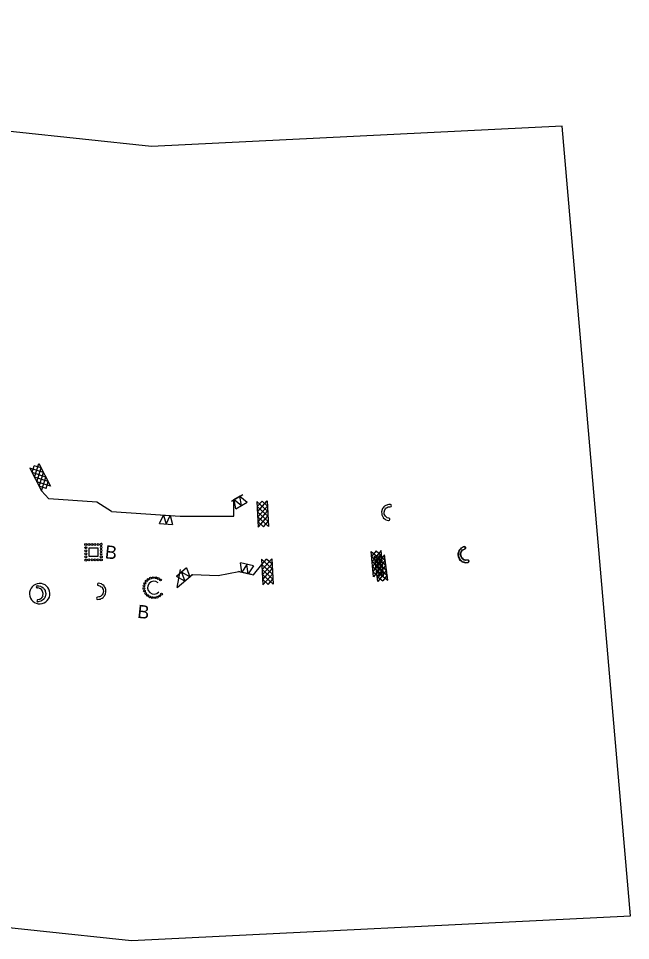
# Model space of a CAD drawing. Extents: x 2283629 to 2286552, y 529718 to 531440.
# Drawn here: x 2285858 to 2286552, y 529718 to 530763 of the extents above; entities that cross this region are included whole.
import ezdxf

# ---------------------------------------------------------------- set-up
doc = ezdxf.new("R2010")
doc.units = 0
for name, color, linetype in [('_CIVIL_CONSTRUCTION', 7, 'Continuous'), ('Draft_Corridor_Graphics_Design', 7, 'Continuous'), ('Draft_Corridor_Graphics_Final', 7, 'Continuous'), ('E_NCDOT_Vertical_Profile_Ground_Line', 7, 'Continuous'), ('P_NCDOT_Terrain_Exterior', 7, 'Continuous'), ('P_NCDOT_Terrain_Model_Triangles', 7, 'Continuous'), ('P_NCDOT_Terrain_Triangle_Vertices', 7, 'Continuous'), ('P_NCDOT_Terrain_Void', 7, 'Continuous'), ('P_RDY_Slope_Stake_Fill_Limits', 7, 'Continuous'), ('P_RDY_TC_Pvmt_Asphalt_Base_Course_Wedge', 7, 'Continuous'), ('P_RDY_TC_Pvmt_Asphalt_Intermediate_Course_Wedge', 7, 'Continuous'), ('P_RDY_TL_Paved_Shoulder_Sub', 7, 'Continuous'), ('P_RDY_TL_Sidewalk', 7, 'Continuous'), ('Scratch_Level_5', 7, 'Continuous')]:
    doc.layers.add(name, color=color, linetype=linetype)

msp = doc.modelspace()

# ---------------------------------------------------------------- linework, layer by layer
at = {"layer": '_CIVIL_CONSTRUCTION'}
msp.add_lwpolyline([(2285237.1, 530763.3), (2285008.8, 530132), (2284997.4, 530131.2), (2285004.2, 530031.4), (2284931, 529916.9), (2285450.5, 529775.1), (2285986, 529718.4), (2286551.7, 529746.5), (2286474.3, 530641.3), (2286008.6, 530618.1), (2285617, 530659.6)], close=True, dxfattribs=at)
at = {"layer": 'Draft_Corridor_Graphics_Final'}
for p, q in [((2286358.9, 530156.6), (2286359.2, 530157.7)), ((2286359.2, 530153.9), (2286359.1, 530154)), ((2286359.5, 530158.8), (2286359.6, 530159)), ((2286365, 530149.2), (2286364.6, 530149.2))]:
    msp.add_line(p, q, dxfattribs=at)
for points in [[(2286362.4, 530164.5), (2286361, 530163.8), (2286359.4, 530163), (2286358.9, 530162.4), (2286358, 530161.4), (2286357, 530160.2), (2286357, 530160.2), (2286356.9, 530159.9), (2286356.9, 530159.7), (2286356.7, 530159), (2286356.4, 530158.1), (2286356.3, 530157.9), (2286356, 530156.8), (2286356, 530155.8), (2286356.3, 530153.1), (2286356.3, 530153.1), (2286357.4, 530150.9), (2286357.9, 530149.9), (2286359, 530149), (2286359.5, 530148.5), (2286360.3, 530147.9), (2286360.3, 530147.9), (2286360.6, 530147.6), (2286360.7, 530147.5), (2286362.4, 530147), (2286363.4, 530146.7), (2286364.2, 530146.5), (2286366, 530146.7), (2286367.5, 530146.9)], [(2286366.8, 530149.4), (2286365, 530149.2), (2286364.6, 530149.2), (2286363.2, 530149.6), (2286362.2, 530149.9), (2286361.1, 530150.9), (2286360.3, 530151.7), (2286359.2, 530153.9), (2286359.1, 530154), (2286358.9, 530156.6), (2286359.2, 530157.7), (2286359.5, 530158.8), (2286359.6, 530159), (2286360.5, 530160.1), (2286361.2, 530161), (2286361.9, 530161.3), (2286363.3, 530162), (2286363.3, 530162)]]:
    msp.add_lwpolyline(points, dxfattribs=at)
for centre, radius, start in [((2286362.8, 530163.2), 1.33, 294.9625), ((2286367.2, 530148.1), 1.3, 286.0751)]:
    msp.add_arc(centre, radius, start, 106.0751, dxfattribs=at)
at = {"layer": 'E_NCDOT_Vertical_Profile_Ground_Line'}
for p, q in [((2286099.1, 530216.3), (2286112, 530223.8)), ((2286104.1, 530207.6), (2286102.3, 530218.2)), ((2286102.3, 530218.2), (2286110.6, 530211.4)), ((2286104.1, 530207.6), (2286117.1, 530215.2)), ((2286110.6, 530211.4), (2286108.8, 530221.9)), ((2286108.8, 530221.9), (2286117.1, 530215.2)), ((2286017.5, 530190.9), (2286022.1, 530200.6)), ((2286018.3, 530200.9), (2286033.3, 530199.7)), ((2286022.1, 530200.6), (2286025, 530190.3)), ((2286025, 530190.3), (2286029.5, 530200)), ((2286029.5, 530200), (2286032.4, 530189.7)), ((2286017.5, 530190.9), (2286032.4, 530189.7)), ((2286124.1, 530143), (2286109.5, 530146.3)), ((2286110.9, 530135.8), (2286109.5, 530146.3)), ((2286116.8, 530144.7), (2286110.9, 530135.8)), ((2286118.2, 530134.1), (2286116.8, 530144.7)), ((2286124.1, 530143), (2286118.2, 530134.1)), ((2286048.2, 530140.7), (2286036.9, 530130.8)), ((2286046.3, 530125.7), (2286036.9, 530130.8)), ((2286052, 530130.7), (2286042.6, 530135.7)), ((2286042.6, 530135.7), (2286046.3, 530125.7)), ((2286054.8, 530133.1), (2286043.5, 530123.3)), ((2286048.2, 530140.7), (2286052, 530130.7)), ((2286121.9, 530133.3), (2286107.3, 530136.6))]:
    msp.add_line(p, q, dxfattribs=at)
at = {"layer": 'P_NCDOT_Terrain_Exterior'}
for p, q in [((2285873.1, 530248.6), (2285875.6, 530256.4)), ((2285883.3, 530253.9), (2285875.6, 530256.4)), ((2285875.7, 530243.5), (2285880.7, 530259)), ((2285880.7, 530259), (2285894, 530233.3)), ((2285886, 530248.7), (2285870.4, 530253.7)), ((2285870.4, 530253.7), (2285883.7, 530228)), ((2285888.7, 530243.6), (2285873.1, 530248.6)), ((2285878.4, 530238.3), (2285883.3, 530253.9)), ((2285881, 530233.2), (2285886, 530248.7)), ((2285891.3, 530238.5), (2285875.7, 530243.5)), ((2285894, 530233.3), (2285878.4, 530238.3)), ((2285883.7, 530228), (2285888.7, 530243.6)), ((2285888.9, 530230.7), (2285891.3, 530238.5)), ((2285888.9, 530230.7), (2285881, 530233.2)), ((2286140.2, 530204.9), (2286128.1, 530215.8)), ((2286128.1, 530215.8), (2286129.6, 530187)), ((2286128.4, 530210.1), (2286133.9, 530216.2)), ((2286128.7, 530204.3), (2286139.6, 530216.5)), ((2286139.9, 530210.8), (2286133.9, 530216.2)), ((2286139.6, 530216.5), (2286141.2, 530187.6)), ((2286140.5, 530199.1), (2286128.4, 530210.1)), ((2286140.9, 530193.4), (2286128.7, 530204.3)), ((2286129, 530198.5), (2286139.9, 530210.7)), ((2286129.3, 530192.8), (2286140.2, 530204.9)), ((2286141.2, 530187.6), (2286129, 530198.5)), ((2286129.6, 530187), (2286140.5, 530199.1)), ((2286135.4, 530187.3), (2286140.9, 530193.4)), ((2286135.4, 530187.3), (2286129.3, 530192.8)), ((2286145.5, 530139.5), (2286133.3, 530150.4)), ((2286133.3, 530150.4), (2286134.9, 530121.6)), ((2286133.6, 530144.7), (2286139.1, 530150.7)), ((2286145.8, 530133.7), (2286133.6, 530144.7)), ((2286134, 530138.9), (2286144.9, 530151)), ((2286134.3, 530133.1), (2286145.2, 530145.3)), ((2286145.1, 530145.3), (2286139.1, 530150.7)), ((2286144.9, 530151), (2286146.4, 530122.2)), ((2286146.1, 530128), (2286134, 530138.9)), ((2286146.4, 530122.2), (2286134.3, 530133.1)), ((2286134.6, 530127.4), (2286145.5, 530139.5)), ((2286134.9, 530121.6), (2286145.8, 530133.7)), ((2286140.7, 530121.9), (2286134.6, 530127.4)), ((2286140.7, 530121.9), (2286146.1, 530128))]:
    msp.add_line(p, q, dxfattribs=at)
at = {"layer": 'P_NCDOT_Terrain_Model_Triangles'}
for p, q in [((2286359.4, 530157.1), (2286359.8, 530158.2)), ((2286359.6, 530154.5), (2286359.6, 530154.5)), ((2286360.2, 530159.3), (2286360.3, 530159.5)), ((2286365.2, 530149.4), (2286364.8, 530149.4))]:
    msp.add_line(p, q, dxfattribs=at)
for points in [[(2286363.3, 530164.8), (2286361.9, 530164.2), (2286360.3, 530163.5), (2286359.8, 530162.9), (2286358.8, 530161.9), (2286357.8, 530160.8), (2286357.8, 530160.8), (2286357.7, 530160.5), (2286357.6, 530160.3), (2286357.3, 530159.6), (2286357, 530158.7), (2286356.9, 530158.5), (2286356.5, 530157.5), (2286356.6, 530156.4), (2286356.7, 530153.8), (2286356.7, 530153.8), (2286357.7, 530151.5), (2286358.2, 530150.5), (2286359.2, 530149.5), (2286359.7, 530149), (2286360.4, 530148.4), (2286360.5, 530148.3), (2286360.8, 530148), (2286360.8, 530148), (2286362.5, 530147.4), (2286363.5, 530147.1), (2286364.3, 530146.8), (2286366.1, 530146.9), (2286367.6, 530147)], [(2286367, 530149.5), (2286365.2, 530149.4), (2286364.8, 530149.4), (2286363.4, 530149.9), (2286362.5, 530150.3), (2286361.4, 530151.3), (2286360.6, 530152.1), (2286359.6, 530154.5), (2286359.6, 530154.5), (2286359.4, 530157.1), (2286359.8, 530158.2), (2286360.2, 530159.3), (2286360.3, 530159.5), (2286361.2, 530160.6), (2286362, 530161.4), (2286362.7, 530161.7), (2286364.2, 530162.3), (2286364.2, 530162.3)]]:
    msp.add_lwpolyline(points, dxfattribs=at)
for centre, radius, start in [((2286363.6, 530163.5), 1.33, 292.2104), ((2286367.3, 530148.3), 1.3, 283.3231)]:
    msp.add_arc(centre, radius, start, 103.3231, dxfattribs=at)
at = {"layer": 'P_NCDOT_Terrain_Triangle_Vertices'}
for p, q in [((2285881.1, 530117.6), (2285879.3, 530117.9)), ((2285881.1, 530117.6), (2285881.4, 530117.5)), ((2285882.7, 530116.8), (2285881.4, 530117.5)), ((2285883.6, 530116.3), (2285882.7, 530116.8)), ((2285884.4, 530115.1), (2285883.6, 530116.3)), ((2285885.1, 530114.1), (2285884.4, 530115.1)), ((2285885.6, 530111.6), (2285885.1, 530114.1)), ((2285885.3, 530109), (2285885.6, 530111.6)), ((2285885.6, 530111.6), (2285885.6, 530111.6)), ((2285879.7, 530104.8), (2285881.2, 530105.1)), ((2285881.2, 530105.1), (2285882, 530105.3)), ((2285882, 530105.3), (2285882.9, 530105.9)), ((2285882.9, 530105.9), (2285884.1, 530106.8)), ((2285884.2, 530107), (2285884.1, 530106.8)), ((2285884.2, 530107), (2285884.7, 530108)), ((2285885.3, 530109), (2285884.7, 530108))]:
    msp.add_line(p, q, dxfattribs=at)
msp.add_lwpolyline([(2285879.1, 530120.4), (2285880.7, 530120.3), (2285882.5, 530120), (2285883.2, 530119.6), (2285884.1, 530119.1), (2285885.7, 530118.2), (2285885.7, 530118.2), (2285885.9, 530117.8), (2285886, 530117.7), (2285886.5, 530117), (2285886.9, 530116.4), (2285887.8, 530115.2), (2285888, 530114.2), (2285888.6, 530111.7), (2285888.6, 530111.7), (2285888.2, 530109.1), (2285888.1, 530108.1), (2285887.5, 530107.1), (2285887.4, 530106.9), (2285886.9, 530106.1), (2285886.5, 530105.5), (2285886.4, 530105.3), (2285886.2, 530105), (2285886.2, 530105), (2285885, 530104.1), (2285883.9, 530103.4), (2285883.2, 530102.9), (2285881.5, 530102.5), (2285880, 530102.1)], dxfattribs=at)
for centre, radius, start, end in [((2285881.8, 530111.5), 11.6, 92.6069, 182.6069), ((2285879.2, 530119.2), 1.3, 92.6069, 272.6069), ((2285881.8, 530111.5), 11.6, 2.6069, 92.6069), ((2285881.8, 530111.5), 11.6, 182.6069, 272.6069), ((2285881.8, 530111.5), 11.6, 272.6069, 2.6069), ((2285880, 530103.4), 1.33, 101.4943, 272.6069)]:
    msp.add_arc(centre, radius, start, end, dxfattribs=at)
at = {"layer": 'P_NCDOT_Terrain_Void'}
for p, q in [((2286260.2, 530130.6), (2286257.5, 530159.4)), ((2286257.5, 530159.4), (2286270.1, 530149)), ((2286263.2, 530159.9), (2286258, 530153.6)), ((2286258, 530153.6), (2286270.6, 530143.2)), ((2286269, 530160.5), (2286258.6, 530147.9)), ((2286269.5, 530154.7), (2286259.1, 530142.1)), ((2286263.2, 530159.9), (2286269.5, 530154.7)), ((2286271.7, 530131.7), (2286269, 530160.5)), ((2286258.6, 530147.9), (2286271.1, 530137.4)), ((2286259.1, 530142.1), (2286271.7, 530131.7)), ((2286270.1, 530149), (2286259.6, 530136.4)), ((2286270.6, 530143.2), (2286260.2, 530130.6)), ((2286259.7, 530136.3), (2286265.9, 530131.1)), ((2286271.1, 530137.4), (2286265.9, 530131.1))]:
    msp.add_line(p, q, dxfattribs=at)
at = {"layer": 'P_RDY_Slope_Stake_Fill_Limits'}
for p, q in [((2285952.5, 530167.3), (2285952.5, 530167.4)), ((2285952.6, 530163.8), (2285952.6, 530163.9)), ((2285952.6, 530160.3), (2285952.6, 530160.4)), ((2285952.7, 530156.8), (2285952.7, 530156.8))]:
    msp.add_line(p, q, dxfattribs=at)
msp.add_lwpolyline([(2285937.7, 530163.4), (2285947.7, 530163.5), (2285947.8, 530153.5), (2285937.8, 530153.4)], close=True, dxfattribs=at)
for centre in [(2285933.9, 530167.1), (2285934, 530163.6), (2285937.4, 530167.2), (2285940.9, 530167.2), (2285944.4, 530167.2), (2285947.9, 530167.3), (2285934, 530160.1), (2285934, 530156.6), (2285934.1, 530153.1), (2285951.6, 530153.3), (2285934.1, 530149.6), (2285937.6, 530149.7), (2285941.1, 530149.7), (2285944.6, 530149.7), (2285948.1, 530149.8), (2285951.6, 530149.8)]:
    msp.add_circle(centre, 1.12, dxfattribs=at)
for centre, start, end in [((2285951.4, 530167.3), 3.4189, 357.803), ((2285951.5, 530163.8), 3.1224, 358.0995), ((2285951.5, 530160.3), 2.7859, 358.436), ((2285951.5, 530156.8), 2.3867, 358.8351)]:
    msp.add_arc(centre, 1.12, start, end, dxfattribs=at)
at = {"layer": 'P_RDY_TC_Pvmt_Asphalt_Base_Course_Wedge'}
for p, q in [((2286272.3, 530204), (2286272.3, 530204)), ((2286273.1, 530206.6), (2286273.8, 530207.5)), ((2286274.5, 530208.4), (2286274.6, 530208.6)), ((2286275.9, 530197.4), (2286275.6, 530197.5)), ((2285950.1, 530120.2), (2285950.4, 530120.1)), ((2285953.4, 530111.2), (2285952.7, 530110.3)), ((2285954, 530113.8), (2285954, 530113.8)), ((2285952, 530109.4), (2285951.9, 530109.2))]:
    msp.add_line(p, q, dxfattribs=at)
for points in [[(2286279.3, 530212.6), (2286277.8, 530212.4), (2286276, 530212.3), (2286275.3, 530211.9), (2286274.1, 530211.3), (2286272.8, 530210.6), (2286272.8, 530210.6), (2286272.5, 530210.3), (2286272.4, 530210.2), (2286271.9, 530209.7), (2286271.3, 530208.9), (2286271.2, 530208.7), (2286270.5, 530207.9), (2286270.2, 530206.9), (2286269.4, 530204.3), (2286269.4, 530204.3), (2286269.6, 530201.8), (2286269.7, 530200.8), (2286270.4, 530199.4), (2286270.7, 530198.9), (2286271.1, 530198), (2286271.1, 530197.9), (2286271.3, 530197.5), (2286271.3, 530197.5), (2286272.8, 530196.4), (2286273.5, 530195.8), (2286274.2, 530195.2), (2286275.9, 530194.7), (2286277.4, 530194.3)], [(2286277.7, 530196.9), (2286275.9, 530197.4), (2286275.6, 530197.5), (2286274.5, 530198.5), (2286273.7, 530199.1), (2286273, 530200.4), (2286272.5, 530201.5), (2286272.3, 530204), (2286272.3, 530204), (2286273.1, 530206.6), (2286273.8, 530207.5), (2286274.5, 530208.4), (2286274.6, 530208.6), (2286275.9, 530209.2), (2286276.9, 530209.7), (2286277.7, 530209.8), (2286279.2, 530209.9), (2286279.2, 530209.9)], [(2285947.4, 530104.9), (2285948.9, 530105.2), (2285950.7, 530105.4), (2285951.4, 530105.8), (2285952.6, 530106.4), (2285953.9, 530107.2), (2285953.9, 530107.2), (2285954.1, 530107.5), (2285954.2, 530107.6), (2285954.6, 530108.2), (2285955.2, 530109), (2285955.4, 530109.2), (2285956, 530110.1), (2285956.3, 530111.1), (2285956.9, 530113.6), (2285956.9, 530113.6), (2285956.6, 530116.2), (2285956.5, 530117.2), (2285955.8, 530118.5), (2285955.4, 530119), (2285955, 530119.9), (2285954.9, 530119.9), (2285954.7, 530120.3), (2285954.7, 530120.4), (2285953.2, 530121.4), (2285952.4, 530122), (2285951.7, 530122.5), (2285950, 530122.9), (2285948.4, 530123.3)], [(2285948.3, 530120.7), (2285950.1, 530120.2), (2285950.4, 530120.1), (2285951.6, 530119.3), (2285952.4, 530118.7), (2285953.1, 530117.4), (2285953.7, 530116.3), (2285954, 530113.8), (2285954, 530113.8), (2285953.4, 530111.2), (2285952.7, 530110.3), (2285952, 530109.4), (2285951.9, 530109.2), (2285950.6, 530108.4), (2285949.7, 530107.9), (2285948.9, 530107.8), (2285947.4, 530107.6), (2285947.4, 530107.6)]]:
    msp.add_lwpolyline(points, dxfattribs=at)
for centre, radius, start, end in [((2286279.2, 530211.2), 1.33, 272.8376, 83.9503), ((2286277.6, 530195.6), 1.3, 263.9503, 83.9503), ((2285948.4, 530122), 1.3, 86.5752, 266.5752), ((2285947.5, 530106.3), 1.33, 95.4625, 266.5752)]:
    msp.add_arc(centre, radius, start, end, dxfattribs=at)
at = {"layer": 'P_RDY_TC_Pvmt_Asphalt_Intermediate_Course_Wedge'}
for centre in [(2286010.3, 530129.6), (2286013.3, 530129.5), (2286000, 530120.3), (2286000.9, 530123.1), (2286002.6, 530125.6), (2286004.8, 530127.6), (2286007.4, 530129), (2286016.2, 530128.6), (2286018.7, 530127), (2285999.9, 530117.3), (2286000.5, 530114.4), (2286001.9, 530111.7), (2286003.9, 530109.5), (2286017.8, 530108.9), (2286020, 530110.9), (2286006.4, 530107.9), (2286009.2, 530107), (2286012.2, 530106.9), (2286015.1, 530107.5)]:
    msp.add_circle(centre, 1.01, dxfattribs=at)
msp.add_arc((2286011.3, 530118.3), 7.26, 49.7259, 319.7171, dxfattribs=at)
at = {"layer": 'P_RDY_TL_Sidewalk'}
for p, q in [((2286265, 530125.3), (2286261.5, 530153.9)), ((2286261.5, 530153.9), (2286274.3, 530143.9)), ((2286267.2, 530154.7), (2286262.2, 530148.2)), ((2286272.9, 530155.4), (2286262.9, 530142.5)), ((2286267.2, 530154.7), (2286273.6, 530149.6)), ((2286276.5, 530126.7), (2286272.9, 530155.4)), ((2286262.2, 530148.2), (2286275.1, 530138.1)), ((2286262.9, 530142.5), (2286275.8, 530132.4)), ((2286273.6, 530149.6), (2286263.6, 530136.7)), ((2286274.3, 530143.9), (2286264.3, 530131)), ((2286263.6, 530136.7), (2286276.5, 530126.7)), ((2286264.4, 530130.9), (2286270.8, 530126)), ((2286275.1, 530138.1), (2286265, 530125.3)), ((2286275.8, 530132.4), (2286270.8, 530126))]:
    msp.add_line(p, q, dxfattribs=at)
at = {"layer": 'Scratch_Level_5'}
msp.add_line((2286037.6, 530118.4), (2286041.5, 530139), dxfattribs=at)
for points in [[(2285963.3, 530204.7), (2285946.4, 530215.2), (2285892.2, 530219), (2285883.7, 530228)], [(2285963.3, 530204.7), (2286041.1, 530199.3), (2286102, 530199.1), (2286102, 530218), (2286109.2, 530222.2)], [(2286037.6, 530118.4), (2286055, 530133.3), (2286084.1, 530131.9), (2286107.5, 530136.5), (2286124.2, 530132.9), (2286133.6, 530144.7)]]:
    msp.add_lwpolyline(points, dxfattribs=at)

# ---------------------------------------------------------------- texts
at = {"layer": 'Draft_Corridor_Graphics_Design'}
msp.add_text('B', height=15, rotation=353.9503, dxfattribs=at).set_placement((2285955.2, 530151.6))
at = {"layer": 'P_RDY_TL_Paved_Shoulder_Sub'}
msp.add_text('B', height=15, rotation=353.9503, dxfattribs=at).set_placement((2285992, 530084.1))

doc.saveas('drawing.dxf')
